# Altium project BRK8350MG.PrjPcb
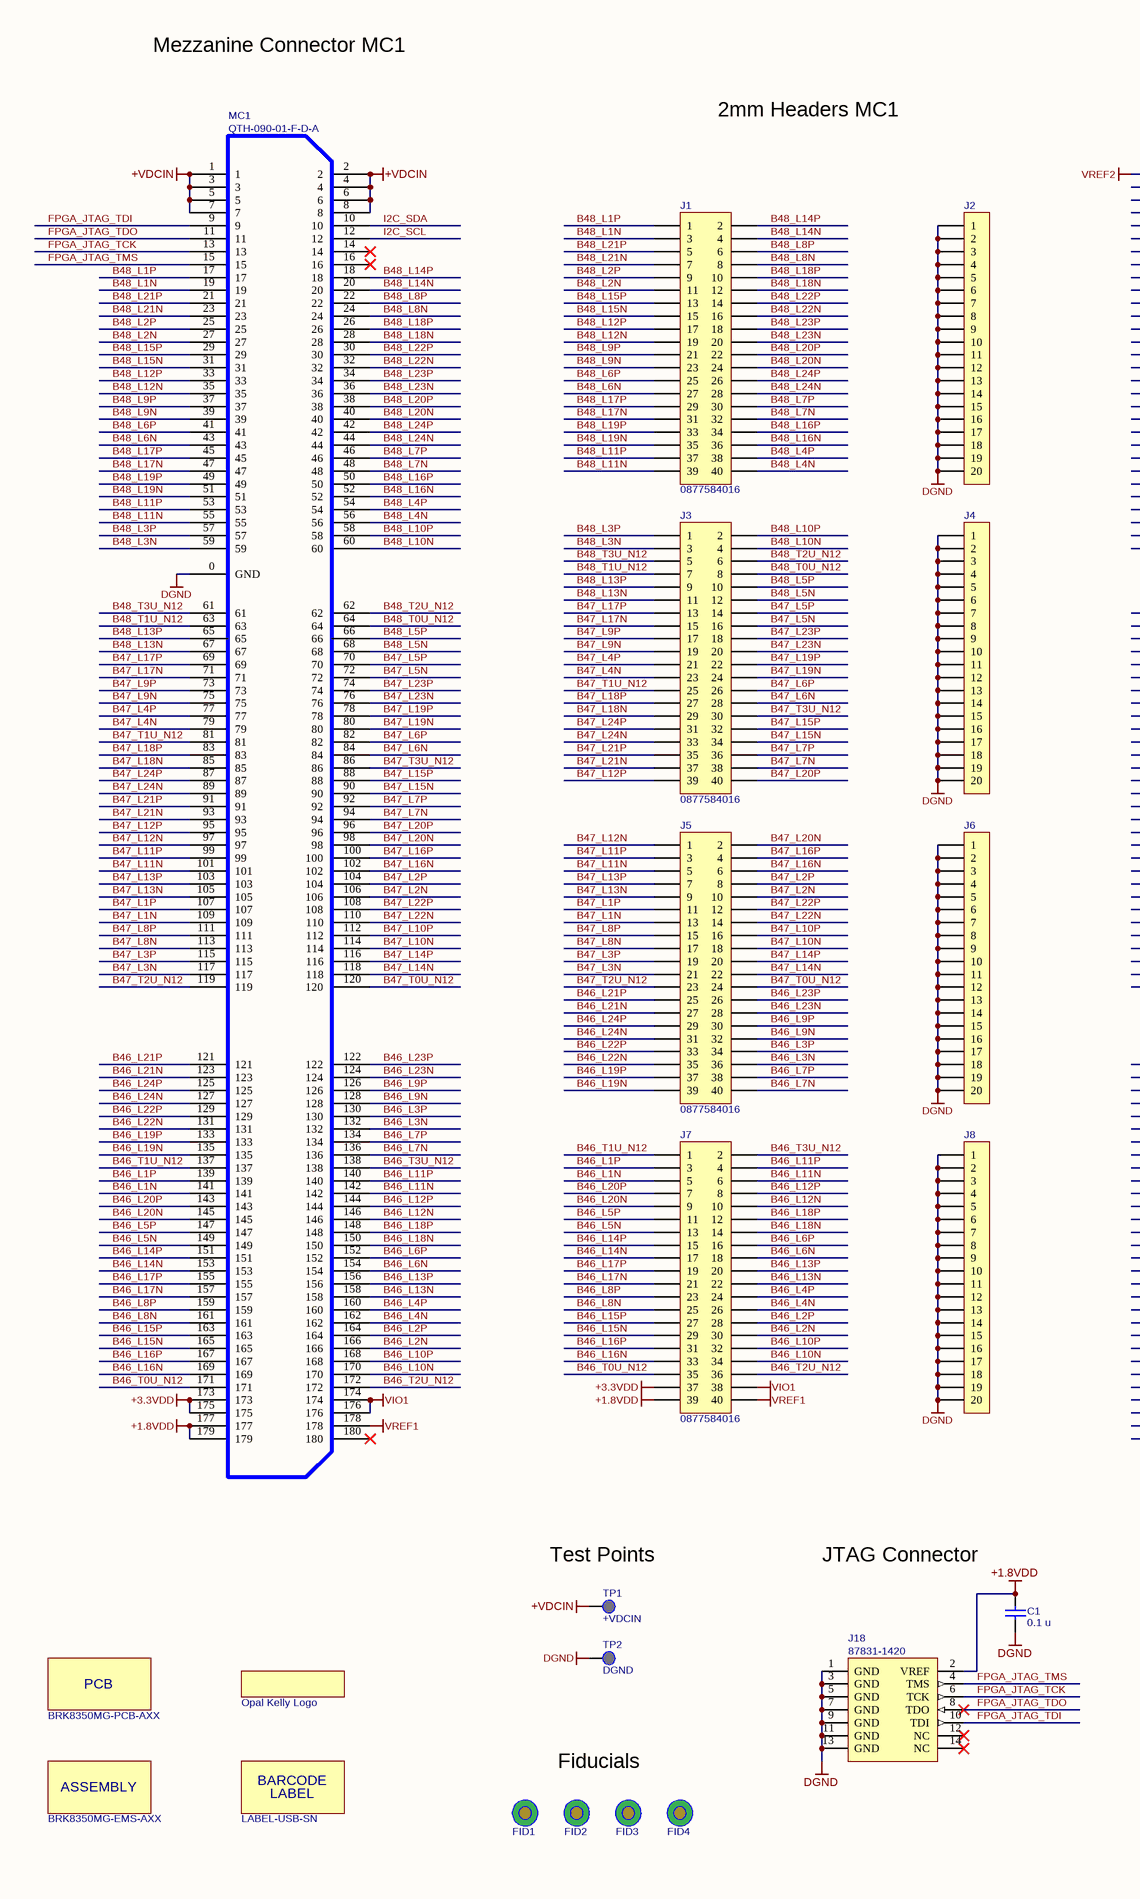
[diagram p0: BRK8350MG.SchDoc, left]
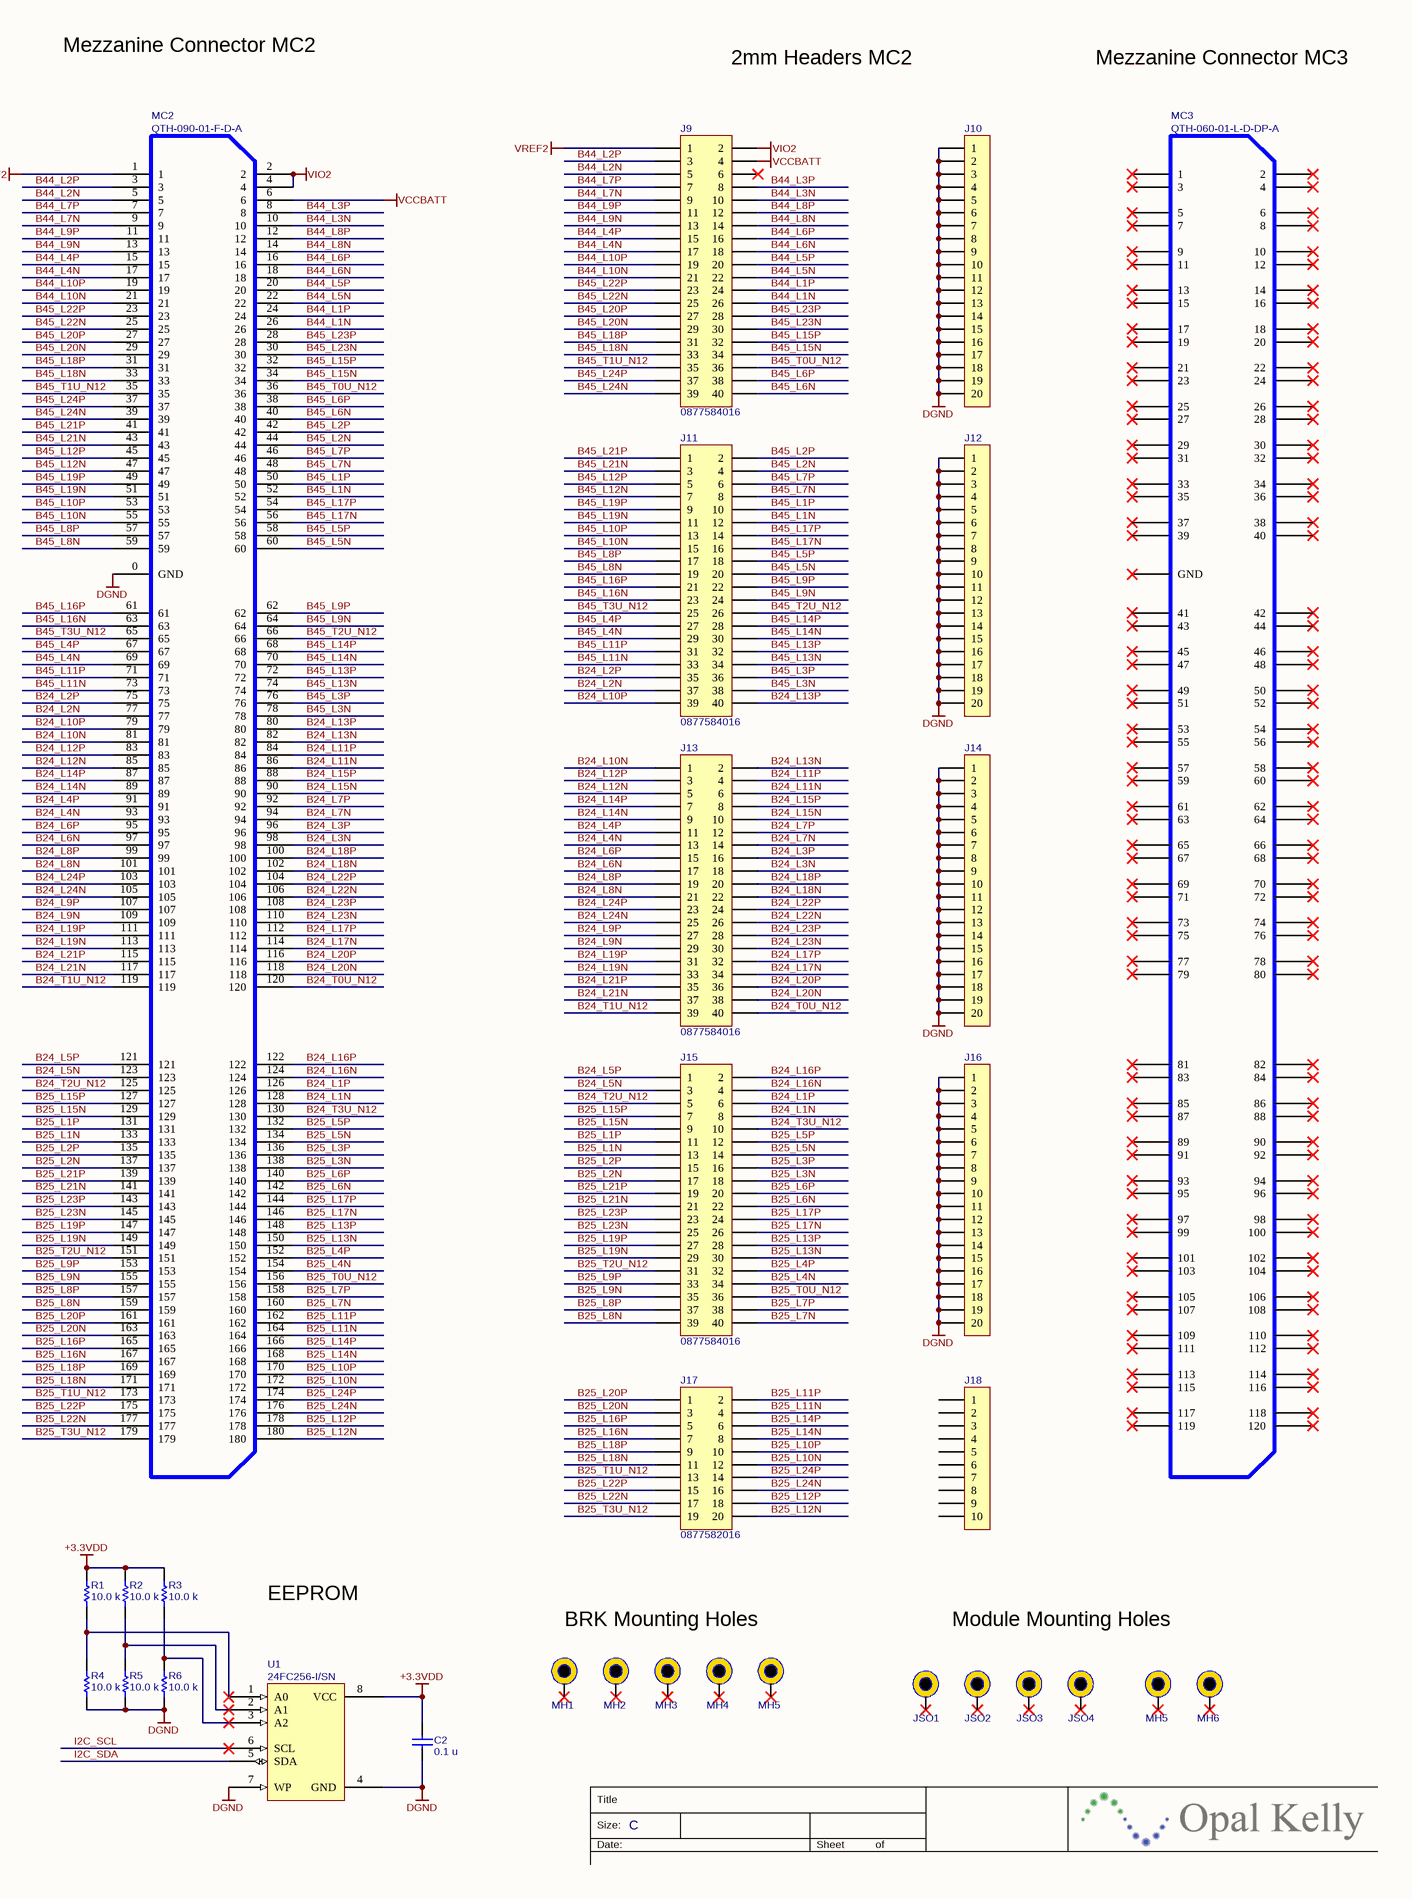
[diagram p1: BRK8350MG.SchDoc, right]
BOM_Revision: 01; Part_Number: BRK8350MG; PCB_Revision: A; VariantBoms: Default=001770
1 sheet, 52 parts. Net scope: hierarchical (ports join the sheet entries above them; power ports are global).
Board file: BRK8350MG.PcbDoc

## Sheet BRK8350MG.SchDoc: BRK8350MG
size C; Author: NDK; Organization: Opal Kelly; Address1: 13500 SW 72nd Ave STE 100; Address2: Portland, OR 97223; Address4: http://www.opalkelly.com; DocumentNumber: xxx; Revision: 1; SheetNumber: 1; SheetTotal: 1

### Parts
(Parts that share a designator on the sheet are numbered #1, #2 ... from top to bottom, then left to right.)
*1  Opal Kelly Logo  [okLogo-23x5]
ASSY1  BRK8350MG-EMS-AXX  (mechanical)
C1  value 0.1 u  [CAPC1005X06A]  (hidden comment: SM-0402, 10%, 10v)
C2  value 0.1 u  [CAPC1005X06A]  (hidden comment: SM-0402, 10%, 10v)
FID1  FIDUCIAL  [FID1MM/2MM-SS]  (value not drawn)
FID2  FIDUCIAL  [FID1MM/2MM-SS]  (value not drawn)
FID3  FIDUCIAL  [FID1MM/2MM-SS]  (value not drawn)
FID4  FIDUCIAL  [FID1MM/2MM-SS]  (value not drawn)
J1  0877584016  [HDR2X20-2MM]
J2  Header, 20-Pin, Single Row  [HDR1X20-2MM]  (value not drawn)
J3  0877584016  [HDR2X20-2MM]
J4  Header, 20-Pin, Single Row  [HDR1X20-2MM]  (value not drawn)
J5  0877584016  [HDR2X20-2MM]
J6  Header, 20-Pin, Single Row  [HDR1X20-2MM]  (value not drawn)
J7  0877584016  [HDR2X20-2MM]
J8  Header, 20-Pin, Single Row  [HDR1X20-2MM]  (value not drawn)
J9  0877584016  [HDR2X20-2MM]
J10  Header, 20-Pin, Single Row  [HDR1X20-2MM]  (value not drawn)
J11  0877584016  [HDR2X20-2MM]
J12  Header, 20-Pin, Single Row  [HDR1X20-2MM]  (value not drawn)
J13  0877584016  [HDR2X20-2MM]
J14  Header, 20-Pin, Single Row  [HDR1X20-2MM]  (value not drawn)
J15  0877584016  [HDR2X20-2MM]
J16  Header, 20-Pin, Single Row  [HDR1X20-2MM]  (value not drawn)
J17  0877582016  [HDR2X10-2MM]
J18#1  Header, 20-Pin, Single Row  [HDR1X10-2MM]  (value not drawn)
J18#2  87831-1420  [XILINX-JTAG]
JSO1  Jack Screw Standoff  [JSO-0515-01]  (value not drawn)
JSO2  Jack Screw Standoff  [JSO-0515-01]  (value not drawn)
JSO3  Jack Screw Standoff  [JSO-0515-01]  (value not drawn)
JSO4  Jack Screw Standoff  [JSO-0515-01]  (value not drawn)
LABEL1  LABEL-USB-SN  (mechanical)
MC1  QTH-090-01-F-D-A  [QTH-090-01-X-D]
MC2  QTH-090-01-F-D-A  [QTH-090-01-X-D]
MC3  QTH-060-01-L-D-DP-A  [QTH-060-01-X-D-DP-A]
MH1  MTG  [MTG-3.2/6.5-PTH]  (value not drawn)
MH2  MTG  [MTG-3.2/6.5-PTH]  (value not drawn)
MH3  MTG  [MTG-3.2/6.5-PTH]  (value not drawn)
MH4  MTG  [MTG-3.2/6.5-PTH]  (value not drawn)
MH5#1  MTG  [MTG-3.2/6.5-PTH]  (value not drawn)
MH5#2  MTG  [MTG-3.2/6.5-PTH]  (value not drawn)
MH6  MTG  [MTG-3.2/6.5-PTH]  (value not drawn)
PCB1  BRK8350MG-PCB-AXX  (mechanical)
R1  value 10.0 k  [RESC1005X06A]  (hidden comment: SM-0402, 1%, 1/16W)
R2  value 10.0 k  [RESC1005X06A]  (hidden comment: SM-0402, 1%, 1/16W)
R3  value 10.0 k  [RESC1005X06A]  (hidden comment: SM-0402, 1%, 1/16W)
R4  value 10.0 k  [RESC1005X06A]  (hidden comment: SM-0402, 1%, 1/16W)
R5  value 10.0 k  [RESC1005X06A]  (hidden comment: SM-0402, 1%, 1/16W)
R6  value 10.0 k  [RESC1005X06A]  (hidden comment: SM-0402, 1%, 1/16W)
TP1  +VDCIN  [TP-PTH-65/100]
TP2  DGND  [TP-PTH-65/100]
U1  24FC256-I/SN  [SO-G8]

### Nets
+1.8VDD: C1.2 J7.39 J18#2.2(VREF) MC1.177 MC1.179
+3.3VDD: C2.2 J7.37 MC1.173 MC1.175 R1.2 R2.2 R3.2 U1.8(VCC)
+VDCIN: MC1.1 MC1.2 MC1.3 MC1.4 MC1.5 MC1.6 MC1.7 MC1.8 TP1.1(PIN)
DGND: C1.1 C2.1 J2.1 J2.2 J2.3 J2.4 J2.5 J2.6 J2.7 J2.8 J2.9 J2.10 J2.11 J2.12 J2.13 J2.14 J2.15 J2.16 J2.17 J2.18 J2.19 J2.20 J4.1 J4.2 J4.3 J4.4 J4.5 J4.6 J4.7 J4.8 J4.9 J4.10 J4.11 J4.12 J4.13 J4.14 J4.15 J4.16 J4.17 J4.18 J4.19 J4.20 J6.1 J6.2 J6.3 J6.4 J6.5 J6.6 J6.7 J6.8 J6.9 J6.10 J6.11 J6.12 J6.13 J6.14 J6.15 J6.16 J6.17 J6.18 J6.19 J6.20 J8.1 J8.2 J8.3 J8.4 J8.5 J8.6 J8.7 J8.8 J8.9 J8.10 J8.11 J8.12 J8.13 J8.14 J8.15 J8.16 J8.17 J8.18 J8.19 J8.20 J10.1 J10.2 J10.3 J10.4 J10.5 J10.6 J10.7 J10.8 J10.9 J10.10 J10.11 J10.12 J10.13 J10.14 J10.15 J10.16 J10.17 J10.18 J10.19 J10.20 J12.1 J12.2 J12.3 J12.4 J12.5 J12.6 J12.7 J12.8 J12.9 J12.10 J12.11 J12.12 J12.13 J12.14 J12.15 J12.16 J12.17 J12.18 J12.19 J12.20 J14.1 J14.2 J14.3 J14.4 J14.5 J14.6 J14.7 J14.8 J14.9 J14.10 J14.11 J14.12 J14.13 J14.14 J14.15 J14.16 J14.17 J14.18 J14.19 J14.20 J16.1 J16.2 J16.3 J16.4 J16.5 J16.6 J16.7 J16.8 J16.9 J16.10 J16.11 J16.12 J16.13 J16.14 J16.15 J16.16 J16.17 J16.18 J16.19 J16.20 J18#2.1(GND) J18#2.3(GND) J18#2.5(GND) J18#2.7(GND) J18#2.9(GND) J18#2.11(GND) J18#2.13(GND) MC1.0(GND) MC2.0(GND) R4.1 R5.1 R6.1 TP2.1(PIN) U1.4(GND) U1.7(WP)
VCCBATT: J9.4 MC2.6
VIO1: J7.38 MC1.174 MC1.176
VIO2: J9.2 MC2.2 MC2.4
VREF1: J7.40 MC1.178
VREF2: J9.1 MC2.1
B24_L1N: J15.8 MC2.128
B24_L1P: J15.6 MC2.126
B24_L2N: J11.37 MC2.77
B24_L2P: J11.35 MC2.75
B24_L3N: J13.18 MC2.98
B24_L3P: J13.16 MC2.96
B24_L4N: J13.13 MC2.93
B24_L4P: J13.11 MC2.91
B24_L5N: J15.3 MC2.123
B24_L5P: J15.1 MC2.121
B24_L6N: J13.17 MC2.97
B24_L6P: J13.15 MC2.95
B24_L7N: J13.14 MC2.94
B24_L7P: J13.12 MC2.92
B24_L8N: J13.21 MC2.101
B24_L8P: J13.19 MC2.99
B24_L9N: J13.29 MC2.109
B24_L9P: J13.27 MC2.107
B24_L10N: J13.1 MC2.81
B24_L10P: J11.39 MC2.79
B24_L11N: J13.6 MC2.86
B24_L11P: J13.4 MC2.84
B24_L12N: J13.5 MC2.85
B24_L12P: J13.3 MC2.83
B24_L13N: J13.2 MC2.82
B24_L13P: J11.40 MC2.80
B24_L14N: J13.9 MC2.89
B24_L14P: J13.7 MC2.87
B24_L15N: J13.10 MC2.90
B24_L15P: J13.8 MC2.88
B24_L16N: J15.4 MC2.124
B24_L16P: J15.2 MC2.122
B24_L17N: J13.34 MC2.114
B24_L17P: J13.32 MC2.112
B24_L18N: J13.22 MC2.102
B24_L18P: J13.20 MC2.100
B24_L19N: J13.33 MC2.113
B24_L19P: J13.31 MC2.111
B24_L20N: J13.38 MC2.118
B24_L20P: J13.36 MC2.116
B24_L21N: J13.37 MC2.117
B24_L21P: J13.35 MC2.115
B24_L22N: J13.26 MC2.106
B24_L22P: J13.24 MC2.104
B24_L23N: J13.30 MC2.110
B24_L23P: J13.28 MC2.108
B24_L24N: J13.25 MC2.105
B24_L24P: J13.23 MC2.103
B24_T0U_N12: J13.40 MC2.120
B24_T1U_N12: J13.39 MC2.119
B24_T2U_N12: J15.5 MC2.125
B24_T3U_N12: J15.10 MC2.130
B25_L1N: J15.13 MC2.133
B25_L1P: J15.11 MC2.131
B25_L2N: J15.17 MC2.137
B25_L2P: J15.15 MC2.135
B25_L3N: J15.18 MC2.138
B25_L3P: J15.16 MC2.136
B25_L4N: J15.34 MC2.154
B25_L4P: J15.32 MC2.152
B25_L5N: J15.14 MC2.134
B25_L5P: J15.12 MC2.132
B25_L6N: J15.22 MC2.142
B25_L6P: J15.20 MC2.140
B25_L7N: J15.40 MC2.160
B25_L7P: J15.38 MC2.158
B25_L8N: J15.39 MC2.159
B25_L8P: J15.37 MC2.157
B25_L9N: J15.35 MC2.155
B25_L9P: J15.33 MC2.153
B25_L10N: J17.12 MC2.172
B25_L10P: J17.10 MC2.170
B25_L11N: J17.4 MC2.164
B25_L11P: J17.2 MC2.162
B25_L12N: J17.20 MC2.180
B25_L12P: J17.18 MC2.178
B25_L13N: J15.30 MC2.150
B25_L13P: J15.28 MC2.148
B25_L14N: J17.8 MC2.168
B25_L14P: J17.6 MC2.166
B25_L15N: J15.9 MC2.129
B25_L15P: J15.7 MC2.127
B25_L16N: J17.7 MC2.167
B25_L16P: J17.5 MC2.165
B25_L17N: J15.26 MC2.146
B25_L17P: J15.24 MC2.144
B25_L18N: J17.11 MC2.171
B25_L18P: J17.9 MC2.169
B25_L19N: J15.29 MC2.149
B25_L19P: J15.27 MC2.147
B25_L20N: J17.3 MC2.163
B25_L20P: J17.1 MC2.161
B25_L21N: J15.21 MC2.141
B25_L21P: J15.19 MC2.139
B25_L22N: J17.17 MC2.177
B25_L22P: J17.15 MC2.175
B25_L23N: J15.25 MC2.145
B25_L23P: J15.23 MC2.143
B25_L24N: J17.16 MC2.176
B25_L24P: J17.14 MC2.174
B25_T0U_N12: J15.36 MC2.156
B25_T1U_N12: J17.13 MC2.173
B25_T2U_N12: J15.31 MC2.151
B25_T3U_N12: J17.19 MC2.179
B44_L1N: J9.26 MC2.26
B44_L1P: J9.24 MC2.24
B44_L2N: J9.5 MC2.5
B44_L2P: J9.3 MC2.3
B44_L3N: J9.10 MC2.10
B44_L3P: J9.8 MC2.8
B44_L4N: J9.17 MC2.17
B44_L4P: J9.15 MC2.15
B44_L5N: J9.22 MC2.22
B44_L5P: J9.20 MC2.20
B44_L6N: J9.18 MC2.18
B44_L6P: J9.16 MC2.16
B44_L7N: J9.9 MC2.9
B44_L7P: J9.7 MC2.7
B44_L8N: J9.14 MC2.14
B44_L8P: J9.12 MC2.12
B44_L9N: J9.13 MC2.13
B44_L9P: J9.11 MC2.11
B44_L10N: J9.21 MC2.21
B44_L10P: J9.19 MC2.19
B45_L1N: J11.12 MC2.52
B45_L1P: J11.10 MC2.50
B45_L2N: J11.4 MC2.44
B45_L2P: J11.2 MC2.42
B45_L3N: J11.38 MC2.78
B45_L3P: J11.36 MC2.76
B45_L4N: J11.29 MC2.69
B45_L4P: J11.27 MC2.67
B45_L5N: J11.20 MC2.60
B45_L5P: J11.18 MC2.58
B45_L6N: J9.40 MC2.40
B45_L6P: J9.38 MC2.38
B45_L7N: J11.8 MC2.48
B45_L7P: J11.6 MC2.46
B45_L8N: J11.19 MC2.59
B45_L8P: J11.17 MC2.57
B45_L9N: J11.24 MC2.64
B45_L9P: J11.22 MC2.62
B45_L10N: J11.15 MC2.55
B45_L10P: J11.13 MC2.53
B45_L11N: J11.33 MC2.73
B45_L11P: J11.31 MC2.71
B45_L12N: J11.7 MC2.47
B45_L12P: J11.5 MC2.45
B45_L13N: J11.34 MC2.74
B45_L13P: J11.32 MC2.72
B45_L14N: J11.30 MC2.70
B45_L14P: J11.28 MC2.68
B45_L15N: J9.34 MC2.34
B45_L15P: J9.32 MC2.32
B45_L16N: J11.23 MC2.63
B45_L16P: J11.21 MC2.61
B45_L17N: J11.16 MC2.56
B45_L17P: J11.14 MC2.54
B45_L18N: J9.33 MC2.33
B45_L18P: J9.31 MC2.31
B45_L19N: J11.11 MC2.51
B45_L19P: J11.9 MC2.49
B45_L20N: J9.29 MC2.29
B45_L20P: J9.27 MC2.27
B45_L21N: J11.3 MC2.43
B45_L21P: J11.1 MC2.41
B45_L22N: J9.25 MC2.25
B45_L22P: J9.23 MC2.23
B45_L23N: J9.30 MC2.30
B45_L23P: J9.28 MC2.28
B45_L24N: J9.39 MC2.39
B45_L24P: J9.37 MC2.37
B45_T0U_N12: J9.36 MC2.36
B45_T1U_N12: J9.35 MC2.35
B45_T2U_N12: J11.26 MC2.66
B45_T3U_N12: J11.25 MC2.65
B46_L1N: J7.5 MC1.141
B46_L1P: J7.3 MC1.139
B46_L2N: J7.30 MC1.166
B46_L2P: J7.28 MC1.164
B46_L3N: J5.36 MC1.132
B46_L3P: J5.34 MC1.130
B46_L4N: J7.26 MC1.162
B46_L4P: J7.24 MC1.160
B46_L5N: J7.13 MC1.149
B46_L5P: J7.11 MC1.147
B46_L6N: J7.18 MC1.154
B46_L6P: J7.16 MC1.152
B46_L7N: J5.40 MC1.136
B46_L7P: J5.38 MC1.134
B46_L8N: J7.25 MC1.161
B46_L8P: J7.23 MC1.159
B46_L9N: J5.32 MC1.128
B46_L9P: J5.30 MC1.126
B46_L10N: J7.34 MC1.170
B46_L10P: J7.32 MC1.168
B46_L11N: J7.6 MC1.142
B46_L11P: J7.4 MC1.140
B46_L12N: J7.10 MC1.146
B46_L12P: J7.8 MC1.144
B46_L13N: J7.22 MC1.158
B46_L13P: J7.20 MC1.156
B46_L14N: J7.17 MC1.153
B46_L14P: J7.15 MC1.151
B46_L15N: J7.29 MC1.165
B46_L15P: J7.27 MC1.163
B46_L16N: J7.33 MC1.169
B46_L16P: J7.31 MC1.167
B46_L17N: J7.21 MC1.157
B46_L17P: J7.19 MC1.155
B46_L18N: J7.14 MC1.150
B46_L18P: J7.12 MC1.148
B46_L19N: J5.39 MC1.135
B46_L19P: J5.37 MC1.133
B46_L20N: J7.9 MC1.145
B46_L20P: J7.7 MC1.143
B46_L21N: J5.27 MC1.123
B46_L21P: J5.25 MC1.121
B46_L22N: J5.35 MC1.131
B46_L22P: J5.33 MC1.129
B46_L23N: J5.28 MC1.124
B46_L23P: J5.26 MC1.122
B46_L24N: J5.31 MC1.127
B46_L24P: J5.29 MC1.125
B46_T0U_N12: J7.35 MC1.171
B46_T1U_N12: J7.1 MC1.137
B46_T2U_N12: J7.36 MC1.172
B46_T3U_N12: J7.2 MC1.138
B47_L1N: J5.13 MC1.109
B47_L1P: J5.11 MC1.107
B47_L2N: J5.10 MC1.106
B47_L2P: J5.8 MC1.104
B47_L3N: J5.21 MC1.117
B47_L3P: J5.19 MC1.115
B47_L4N: J3.23 MC1.79
B47_L4P: J3.21 MC1.77
B47_L5N: J3.16 MC1.72
B47_L5P: J3.14 MC1.70
B47_L6N: J3.28 MC1.84
B47_L6P: J3.26 MC1.82
B47_L7N: J3.38 MC1.94
B47_L7P: J3.36 MC1.92
B47_L8N: J5.17 MC1.113
B47_L8P: J5.15 MC1.111
B47_L9N: J3.19 MC1.75
B47_L9P: J3.17 MC1.73
B47_L10N: J5.18 MC1.114
B47_L10P: J5.16 MC1.112
B47_L11N: J5.5 MC1.101
B47_L11P: J5.3 MC1.99
B47_L12N: J5.1 MC1.97
B47_L12P: J3.39 MC1.95
B47_L13N: J5.9 MC1.105
B47_L13P: J5.7 MC1.103
B47_L14N: J5.22 MC1.118
B47_L14P: J5.20 MC1.116
B47_L15N: J3.34 MC1.90
B47_L15P: J3.32 MC1.88
B47_L16N: J5.6 MC1.102
B47_L16P: J5.4 MC1.100
B47_L17N: J3.15 MC1.71
B47_L17P: J3.13 MC1.69
B47_L18N: J3.29 MC1.85
B47_L18P: J3.27 MC1.83
B47_L19N: J3.24 MC1.80
B47_L19P: J3.22 MC1.78
B47_L20N: J5.2 MC1.98
B47_L20P: J3.40 MC1.96
B47_L21N: J3.37 MC1.93
B47_L21P: J3.35 MC1.91
B47_L22N: J5.14 MC1.110
B47_L22P: J5.12 MC1.108
B47_L23N: J3.20 MC1.76
B47_L23P: J3.18 MC1.74
B47_L24N: J3.33 MC1.89
B47_L24P: J3.31 MC1.87
B47_T0U_N12: J5.24 MC1.120
B47_T1U_N12: J3.25 MC1.81
B47_T2U_N12: J5.23 MC1.119
B47_T3U_N12: J3.30 MC1.86
B48_L1N: J1.3 MC1.19
B48_L1P: J1.1 MC1.17
B48_L2N: J1.11 MC1.27
B48_L2P: J1.9 MC1.25
B48_L3N: J3.3 MC1.59
B48_L3P: J3.1 MC1.57
B48_L4N: J1.40 MC1.56
B48_L4P: J1.38 MC1.54
B48_L5N: J3.12 MC1.68
B48_L5P: J3.10 MC1.66
B48_L6N: J1.27 MC1.43
B48_L6P: J1.25 MC1.41
B48_L7N: J1.32 MC1.48
B48_L7P: J1.30 MC1.46
B48_L8N: J1.8 MC1.24
B48_L8P: J1.6 MC1.22
B48_L9N: J1.23 MC1.39
B48_L9P: J1.21 MC1.37
B48_L10N: J3.4 MC1.60
B48_L10P: J3.2 MC1.58
B48_L11N: J1.39 MC1.55
B48_L11P: J1.37 MC1.53
B48_L12N: J1.19 MC1.35
B48_L12P: J1.17 MC1.33
B48_L13N: J3.11 MC1.67
B48_L13P: J3.9 MC1.65
B48_L14N: J1.4 MC1.20
B48_L14P: J1.2 MC1.18
B48_L15N: J1.15 MC1.31
B48_L15P: J1.13 MC1.29
B48_L16N: J1.36 MC1.52
B48_L16P: J1.34 MC1.50
B48_L17N: J1.31 MC1.47
B48_L17P: J1.29 MC1.45
B48_L18N: J1.12 MC1.28
B48_L18P: J1.10 MC1.26
B48_L19N: J1.35 MC1.51
B48_L19P: J1.33 MC1.49
B48_L20N: J1.24 MC1.40
B48_L20P: J1.22 MC1.38
B48_L21N: J1.7 MC1.23
B48_L21P: J1.5 MC1.21
B48_L22N: J1.16 MC1.32
B48_L22P: J1.14 MC1.30
B48_L23N: J1.20 MC1.36
B48_L23P: J1.18 MC1.34
B48_L24N: J1.28 MC1.44
B48_L24P: J1.26 MC1.42
B48_T0U_N12: J3.8 MC1.64
B48_T1U_N12: J3.7 MC1.63
B48_T2U_N12: J3.6 MC1.62
B48_T3U_N12: J3.5 MC1.61
FPGA_JTAG_TCK: J18#2.6(TCK) MC1.13
FPGA_JTAG_TDI: J18#2.10(TDI) MC1.9
FPGA_JTAG_TDO: J18#2.8(TDO) MC1.11
FPGA_JTAG_TMS: J18#2.4(TMS) MC1.15
I2C_SCL: MC1.12 U1.6(SCL)
I2C_SDA: MC1.10 U1.5(SDA)
NetR1_1: R1.1 R4.2 U1.1(A0)
NetR2_1: R2.1 R5.2 U1.2(A1)
NetR3_1: R3.1 R6.2 U1.3(A2)

Not connected (* = marked no-connect by the designer): J9 6*; J18#1 1 2 3 4 5 6 7 8 9 10; J18#2 12(NC)* 14(NC)*; JSO1 1*; JSO2 1*; JSO3 1*; JSO4 1*; MC1 14* 16* 180*; MC3 0(GND)* 1* 2* 3* 4* 5* 6* 7* 8* 9* 10* 11* 12* 13* 14* 15* 16* 17* 18* 19* 20* 21* 22* 23* 24* 25* 26* 27* 28* 29* 30* 31* 32* 33* 34* 35* 36* 37* 38* 39* 40* 41* 42* 43* 44* 45* 46* 47* 48* 49* 50* 51* 52* 53* 54* 55* 56* 57* 58* 59* 60* 61* 62* 63* 64* 65* 66* 67* 68* 69* 70* 71* 72* 73* 74* 75* 76* 77* 78* 79* 80* 81* 82* 83* 84* 85* 86* 87* 88* 89* 90* 91* 92* 93* 94* 95* 96* 97* 98* 99* 100* 101* 102* 103* 104* 105* 106* 107* 108* 109* 110* 111* 112* 113* 114* 115* 116* 117* 118* 119* 120*; MH1 1*; MH2 1*; MH3 1*; MH4 1*; MH5#1 1*; MH5#2 1*; MH6 1*

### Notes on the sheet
- Mezzanine Connector MC1
- Mezzanine Connector MC2
- 2mm Headers MC1
- 2mm Headers MC2
- Mezzanine Connector MC3
- (near TP1) Test Points
- JTAG Connector
- EEPROM
- BRK Mounting Holes
- Module Mounting Holes
- Fiducials
- Title
- Size:
- Date:
- C
- Sheet
- of

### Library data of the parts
*1 = OKLOGO: partnumber: ALIGNI_IGNORE
ASSY1 = 002005: Assembly Service; Partnumber: 002005; manufacturer: PCB Assembly Cost
C1 = 000070: Partnumber: 000070; manufacturer: Kemet; manufacturer_pn: C0402C104K8PACTU; ValueFloat: 1E-7; id: 750; inventory_price: 0.0023; reorder_quantity: 70000; x_tolerance: 10
C2 = 000070: Partnumber: 000070; manufacturer: Kemet; manufacturer_pn: C0402C104K8PACTU; ValueFloat: 1E-7; id: 750; inventory_price: 0.0023; reorder_quantity: 70000; x_max_operating_temp: 85; x_min_operating_temp: -55; x_tolerance: 10
FID1-FID4 = FIDUCIAL: PCB fiducial; partnumber: ALIGNI_IGNORE
J1 J3 J5 J7 J9 J11 J13 J15 = 000583: Partnumber: 000583; manufacturer: Molex
J2 J4 J6 J8 J10 J12 J14 J16 = 001334: PartNumber: 001334; manufacturer: 3M; manufacturer_pn: 951120-8622-AR
J17 = 001338: Partnumber: 001338; manufacturer: Molex
J18#1 = 002002: PartNumber: 002002; manufacturer: 3M; manufacturer_pn: 951110-8622-AR
J18#2 = 000541: 2mm header, shrouded; Manufacturer: Molex; partnumber: 000541; Description 2: Dual-row, 14-pos, Xilinx JTAG compatible
JSO1-JSO4 = 001879: Mounting hole; Partnumber: 001879; manufacturer: Samtec
LABEL1 = 000605: Barcode label; Partnumber: 000605; manufacturer: Generic Printer; description: Barcode serial number labels for USB devices
MC1 MC2 = 000876: 0.5mm Double Row High Speed Socket Assembly; Partnumber: 000876; manufacturer: Samtec; id: 17471; inventory_price: 8.87
MC3 = 001769: Partnumber: 001769; manufacturer: Samtec
MH1-MH4 MH5#1 MH5#2 MH6 = MTG: Mounting hole; partnumber: ALIGNI_IGNORE
PCB1 = 002004: PCB; Partnumber: 002004; manufacturer: Generic PCB Manufacturer
R1-R6 = 001521: Partnumber: 001521; manufacturer: Vishay; manufacturer_pn: CRCW040210K0FKED; ValueFloat: 10000; id: 154248; inventory_price: 0.0016; x_tolerance: 1
TP1 TP2 = TP-PTH-65/100: Test point, plated through-hole, 65/100mil; partnumber: ALIGNI_IGNORE
U1 = 000842: Partnumber: 000842; manufacturer: Microchip; id: 14766; inventory_price: 0.39; reorder_quantity: 600

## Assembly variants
Default: not fitted C2 R1 R2 R3 R4 R5 R6 U1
